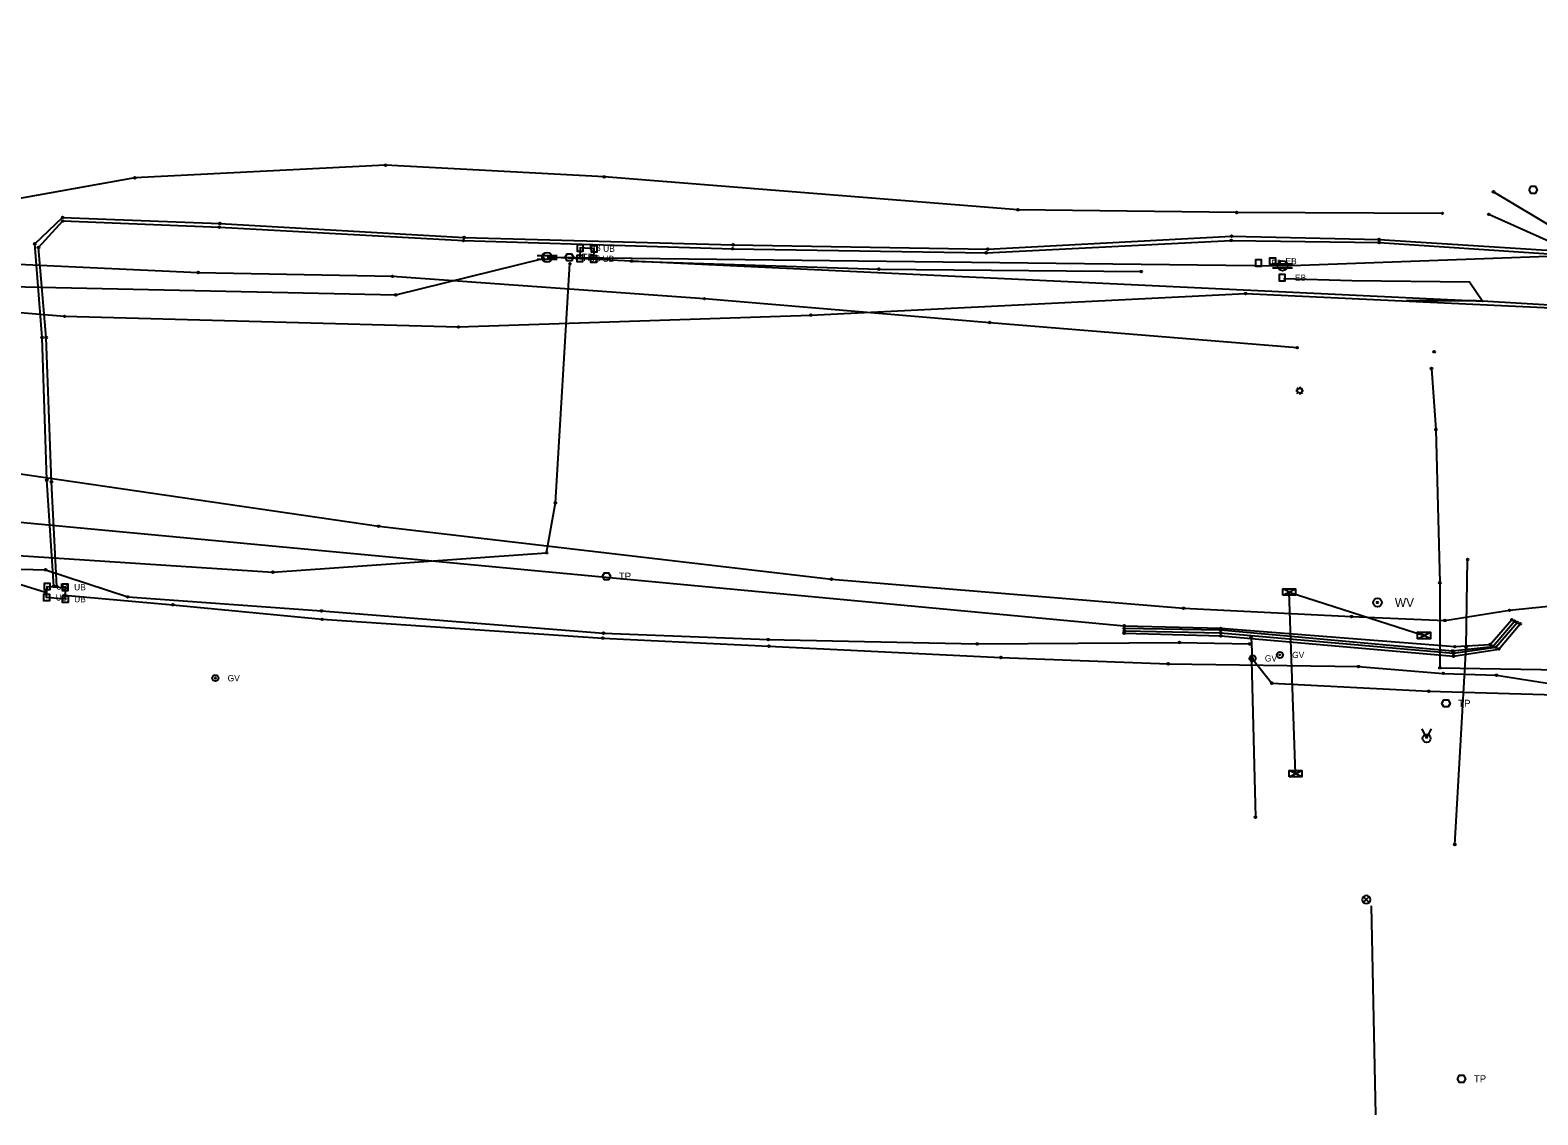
# Model space of a CAD drawing. Extents: x 20500343 to 20505311, y 7953484 to 7954193.
# Drawn here: x 20500991.2 to 20501326.9, y 7953798 to 7954039.6 of the extents above; entities that cross this region are included whole.
import ezdxf

# ---------------------------------------------------------------- set-up
doc = ezdxf.new("R2010")
doc.units = 0
for name, color, linetype in [('C-PROP-LINE-LOT', 7, 'Continuous'), ('V-ANNO-BNDY', 7, 'Continuous'), ('V-ANNO-NOTE', 7, 'Continuous'), ('V-CTRL-HVPT', 7, 'Continuous'), ('V-MON-FND', 7, 'Continuous'), ('V-SITE-FENC', 7, 'Continuous'), ('V-SSWR-STRC', 7, 'Continuous'), ('VF-NODE-MISC', 7, 'Continuous')]:
    doc.layers.add(name, color=color, linetype=linetype)

msp = doc.modelspace()

# ---------------------------------------------------------------- linework, layer by layer
at = {"layer": 'C-PROP-LINE-LOT'}
msp.add_line((20501289.71, 7953844.5), (20501290.73, 7953797.96), dxfattribs=at)
for points in [[(20500406.47, 7954039.57), (20500466.05, 7954034.11), (20500535.84, 7954027.4), (20500662.16, 7954017.11), (20500704.07, 7954013.07), (20500745.63, 7954009.37), (20500792.32, 7954005.22), (20500811.87, 7954003.45), (20500860.59, 7953999.05), (20500920.01, 7953993.63), (20500957.01, 7953989.31), (20500990.1, 7953987.34), (20501028.58, 7953985.6), (20501071.83, 7953984.74), (20501141.27, 7953979.76), (20501204.8, 7953974.46), (20501273.24, 7953968.85)], [(20500542.46, 7954022.99), (20500657.16, 7954010.94), (20500703.46, 7954006.71), (20500768.23, 7954003.33), (20500815.45, 7953998.2), (20500888.96, 7953989.5), (20500955.53, 7953983.16), (20501072.58, 7953980.59), (20501105.36, 7953988.74)], [(20500542.46, 7954013.94), (20500614.61, 7954008.93), (20500657.56, 7954005.52), (20500702.03, 7954001.63), (20500823.93, 7953990.08), (20500894.24, 7953984.51), (20500998.83, 7953975.83), (20501086.53, 7953973.45), (20501164.96, 7953976.11), (20501261.79, 7953980.89), (20501339.33, 7953977.27), (20501419.74, 7953970.03), (20501525.89, 7953965.34), (20501551.15, 7953963.49), (20501624.16, 7953957.55)], [(20501305.59, 7953998.76), (20501259.79, 7953998.96), (20501211.09, 7953999.57), (20501118.97, 7954006.88), (20501070.28, 7954009.47), (20501014.48, 7954006.68), (20500962.69, 7953997.37), (20500913.01, 7953999.39), (20500862.37, 7954004.75), (20500819.48, 7954008.4), (20500817.42, 7954012.31)], [(20501316.97, 7954003.56), (20501331.13, 7953995.08), (20501366.04, 7953982.93), (20501414.04, 7953978.62), (20501439.53, 7953975.27), (20501515.39, 7953971.55), (20501543.03, 7953969.36), (20501590.25, 7953966.08), (20501636.14, 7953963.16), (20501689.01, 7953958.28), (20501726.44, 7953956.52), (20501746.18, 7953958.43), (20501775.61, 7953959.04)], [(20500996.43, 7953915.71), (20500994.86, 7953939.31), (20500993.84, 7953971.13), (20500992.21, 7953991.99), (20500998.39, 7953997.86), (20501033.4, 7953996.49), (20501087.77, 7953993.38), (20501147.66, 7953991.76), (20501204.37, 7953990.78), (20501258.68, 7953993.69), (20501291.5, 7953992.96), (20501367.31, 7953988.1), (20501415.06, 7953984.51), (20501437.58, 7953981.75), (20501512.96, 7953981.34), (20501564.43, 7953975.75), (20501615.72, 7953972.77), (20501679.29, 7953965.51), (20501737.55, 7953960.19), (20501775.55, 7953956.71)], [(20501315.95, 7953998.55), (20501330.06, 7953992.29), (20501366.28, 7953980.24), (20501414.18, 7953976.37), (20501439.46, 7953973.28), (20501446.74, 7953968.11), (20501452.28, 7953949.16), (20501456.12, 7953922.73), (20501455.01, 7953897.31), (20501452.69, 7953873.02), (20501450.67, 7953841.46)], [(20500997.07, 7953915.68), (20500995.89, 7953938.94), (20500994.71, 7953971.1), (20500993, 7953991.18), (20500998.42, 7953997.06), (20501033.28, 7953995.67), (20501087.63, 7953992.68), (20501147.58, 7953990.88), (20501204.03, 7953989.96), (20501258.58, 7953992.74), (20501291.52, 7953992.27), (20501367.1, 7953987.19), (20501414.72, 7953983.8), (20501438.34, 7953980.22), (20501512.8, 7953980.63), (20501564.51, 7953974.63), (20501615.49, 7953972.13), (20501679.12, 7953964.62), (20501737.42, 7953959.32), (20501775.43, 7953955.89)], [(20501106.27, 7953988.97), (20501270.01, 7953987.09), (20501461.7, 7953994.07)], [(20501106.16, 7953923.17), (20501108.1, 7953934.3), (20501111.35, 7953987.56)], [(20501270.23, 7953984.25), (20501285.41, 7953983.78), (20501311.63, 7953983.5), (20501314.64, 7953979.15), (20501106.27, 7953988.97)], [(20501125.08, 7953988.13), (20501180.15, 7953986.34), (20501238.55, 7953985.78)], [(20501297.64, 7953979.33), (20501313.17, 7953979.32), (20501384.83, 7953975.15), (20501444.4, 7953969.74), (20501500.9, 7953964.74), (20501525.63, 7953962.76), (20501557.44, 7953960.37)], [(20500520.98, 7953977.28), (20500560.2, 7953972.18), (20500580.11, 7953968.09), (20500618.43, 7953964.47), (20500633.81, 7953963.45), (20500668.21, 7953960.34), (20500693.49, 7953957.8), (20500747.72, 7953955.96), (20500802.14, 7953953.65), (20500876.21, 7953950.48), (20500928.48, 7953945.92), (20500984.31, 7953941.41), (20501068.76, 7953929.07), (20501169.59, 7953917.28), (20501247.95, 7953910.8), (20501285.38, 7953908.94), (20501306.14, 7953908.1), (20501320.57, 7953910.34), (20501331.41, 7953911.48)], [(20500469.9, 7953970.65), (20500505.35, 7953968.7), (20500522.37, 7953967.11), (20500565.63, 7953966.99), (20500619.43, 7953961.41), (20500633.65, 7953961.99), (20500668.11, 7953958.55), (20500688.24, 7953956.38), (20500722.3, 7953952.32), (20500751.12, 7953948.12), (20500793.42, 7953946.39), (20500829.09, 7953943.31), (20500867.84, 7953939.12), (20500927.83, 7953934.54), (20500971.05, 7953923.41), (20500978.23, 7953919.45), (20500994.58, 7953914.36)], [(20500542.27, 7953966.39), (20500567.09, 7953964.35), (20500611.73, 7953958.49), (20500625.61, 7953958.17), (20500630.34, 7953957.23), (20500641.04, 7953945.21), (20500677.24, 7953941.24), (20500710.61, 7953939.53), (20500749.41, 7953937.97), (20500784.55, 7953934.93), (20500831.09, 7953929.74), (20500863.89, 7953925.18), (20500925.53, 7953920.74), (20500962.01, 7953920.15), (20500972.45, 7953919.98), (20500994.6, 7953919.38), (20501012.87, 7953913.32), (20501056.03, 7953910.21), (20501118.83, 7953905.25), (20501155.51, 7953903.82), (20501202, 7953902.86), (20501247.06, 7953903.19), (20501262.67, 7953902.86)], [(20501303.19, 7953964.19), (20501304.16, 7953950.59), (20501305.04, 7953916.44), (20501305.05, 7953897.56), (20501336.58, 7953897.02), (20501416.18, 7953891.49), (20501472.56, 7953887.01)], [(20500798.27, 7953938.75), (20500868.59, 7953931.82), (20500926.05, 7953926.61), (20501045.21, 7953918.84), (20501106.16, 7953923.17)], [(20500968.33, 7953931.91), (20501234.75, 7953906.92), (20501256.26, 7953906.33), (20501308.38, 7953902.25), (20501316.23, 7953902.74), (20501321.08, 7953908.26)], [(20501308.36, 7953858.15), (20501310.89, 7953902.15), (20501311.23, 7953921.69)], [(20500998.83, 7953913.68), (20501022.94, 7953911.59), (20501056.17, 7953908.34), (20501118.67, 7953904.16), (20501155.66, 7953902.37), (20501207.31, 7953899.83), (20501244.54, 7953898.43), (20501286.93, 7953897.81), (20501305.79, 7953896.3), (20501317.66, 7953895.88), (20501451.4, 7953874.84), (20501522.75, 7953865.03), (20501559.04, 7953858.38), (20501592.55, 7953848.31), (20501608.82, 7953843.84), (20501626.02, 7953848.37), (20501659.58, 7953855.08), (20501681.27, 7953854.69), (20501701.7, 7953853.44), (20501722.46, 7953851.13), (20501765.84, 7953847.22)], [(20501272.89, 7953873.96), (20501271.49, 7953914.42), (20501301.52, 7953904.73)], [(20501234.76, 7953905.25), (20501256.28, 7953904.66), (20501308.05, 7953900.12), (20501318.18, 7953901.72), (20501322.91, 7953907.33)], [(20501234.77, 7953906.33), (20501256.28, 7953905.98), (20501307.87, 7953901.29), (20501316.83, 7953902.31), (20501321.64, 7953907.92)], [(20501234.79, 7953905.75), (20501256.21, 7953905.36), (20501308.08, 7953900.78), (20501317.52, 7953902.1), (20501322.24, 7953907.64)], [(20501263.02, 7953904.3), (20501263.23, 7953899.59), (20501267.6, 7953894.11), (20501302.56, 7953892.31), (20501415.59, 7953889.07), (20501446.52, 7953886.98), (20501469.46, 7953879.66), (20501523.96, 7953857.45), (20501561.35, 7953852.73), (20501613.91, 7953852.27), (20501680.57, 7953850.9), (20501710.93, 7953846.81), (20501733.66, 7953845.08), (20501733.32, 7953834.72), (20501764.02, 7953830.92)], [(20501263.07, 7953899.12), (20501263.97, 7953864.25)]]:
    msp.add_lwpolyline(points, dxfattribs=at)
at = {"layer": 'V-ANNO-BNDY'}
for p, q in [((20501269.63, 7953984.27), (20501269.63, 7953984.27)), ((20501268.96, 7953969.75), (20501268.96, 7953969.75)), ((20501303.76, 7953967.94), (20501303.76, 7953967.94)), ((20501273.1, 7953959.9), (20501273.1, 7953959.9))]:
    msp.add_line(p, q, dxfattribs=at)
for centre, radius in [((20501263.33, 7953899.64), 0.685), ((20501269.41, 7953900.4), 0.685), ((20501269.41, 7953900.4), 0.114), ((20501263.33, 7953899.64), 0.114), ((20501032.39, 7953895.23), 0.685), ((20501032.39, 7953895.23), 0.114)]:
    msp.add_circle(centre, radius, dxfattribs=at)
at = {"layer": 'V-ANNO-NOTE'}
for centre in [(20501070.28, 7954009.47), (20501014.48, 7954006.68), (20501118.97, 7954006.88), (20501316.97, 7954003.56), (20500998.39, 7953997.86), (20501211.09, 7953999.57), (20501259.79, 7953998.96), (20501305.59, 7953998.76), (20501315.95, 7953998.55), (20500998.42, 7953997.06), (20501033.28, 7953995.67), (20501033.4, 7953996.49), (20500992.21, 7953991.99), (20500993, 7953991.18), (20501087.63, 7953992.68), (20501087.77, 7953993.38), (20501147.58, 7953990.88), (20501147.66, 7953991.76), (20501204.37, 7953990.78), (20501258.58, 7953992.74), (20501258.68, 7953993.69), (20501291.5, 7953992.96), (20501291.52, 7953992.27), (20501105.36, 7953988.74), (20501111.35, 7953987.56), (20501125.08, 7953988.13), (20501204.03, 7953989.96), (20501028.58, 7953985.6), (20501071.83, 7953984.74), (20501180.15, 7953986.34), (20501238.55, 7953985.78), (20501261.79, 7953980.89), (20501072.58, 7953980.59), (20501141.27, 7953979.76), (20500998.83, 7953975.83), (20501164.96, 7953976.11), (20501204.8, 7953974.46), (20500993.84, 7953971.13), (20500994.71, 7953971.1), (20501086.53, 7953973.45), (20501273.24, 7953968.85), (20501303.76, 7953967.94), (20501303.19, 7953964.19), (20501304.16, 7953950.59), (20500994.86, 7953939.31), (20500995.89, 7953938.94), (20501108.1, 7953934.3), (20501068.76, 7953929.07), (20501106.16, 7953923.17), (20501106.16, 7953923.17), (20501311.23, 7953921.69), (20500994.6, 7953919.38), (20501045.21, 7953918.84), (20501169.59, 7953917.28), (20500994.58, 7953914.36), (20500996.43, 7953915.71), (20500997.07, 7953915.68), (20500998.83, 7953913.68), (20501305.04, 7953916.44), (20501012.87, 7953913.32), (20501022.94, 7953911.59), (20501056.03, 7953910.21), (20501247.95, 7953910.8), (20501320.57, 7953910.34), (20501056.17, 7953908.34), (20501234.75, 7953906.92), (20501285.38, 7953908.94), (20501306.14, 7953908.1), (20501321.08, 7953908.26), (20501321.64, 7953907.92), (20501322.24, 7953907.64), (20501322.91, 7953907.33), (20501118.67, 7953904.16), (20501118.83, 7953905.25), (20501155.51, 7953903.82), (20501234.76, 7953905.25), (20501234.77, 7953906.33), (20501234.79, 7953905.75), (20501256.21, 7953905.36), (20501256.26, 7953906.33), (20501256.28, 7953905.98), (20501256.28, 7953904.66), (20501263.02, 7953904.3), (20501155.66, 7953902.37), (20501202, 7953902.86), (20501247.06, 7953903.19), (20501262.67, 7953902.86), (20501307.87, 7953901.29), (20501308.05, 7953900.12), (20501308.08, 7953900.78), (20501308.38, 7953902.25), (20501310.89, 7953902.15), (20501316.23, 7953902.74), (20501316.83, 7953902.31), (20501317.52, 7953902.1), (20501318.18, 7953901.72), (20501207.31, 7953899.83), (20501244.54, 7953898.43), (20501263.07, 7953899.12), (20501263.23, 7953899.59), (20501286.93, 7953897.81), (20501305.05, 7953897.56), (20501267.6, 7953894.11), (20501305.79, 7953896.3), (20501317.66, 7953895.88), (20501302.56, 7953892.31), (20501263.97, 7953864.25), (20501308.36, 7953858.15)]:
    msp.add_circle(centre, 0.2, dxfattribs=at)
at = {"layer": 'V-CTRL-HVPT'}
for p, q in [((20501104.07, 7953989.41), (20501108.47, 7953989.41)), ((20501104.07, 7953988.53), (20501108.47, 7953988.53)), ((20501267.81, 7953987.53), (20501272.21, 7953987.53)), ((20501267.81, 7953986.65), (20501272.21, 7953986.65)), ((20501272.97, 7953959.28), (20501273.3, 7953959.28)), ((20501273.23, 7953959.9), (20501273.46, 7953959.67)), ((20501273.23, 7953958.67), (20501273.46, 7953958.9)), ((20501273.84, 7953960.15), (20501273.84, 7953959.82)), ((20501273.84, 7953958.74), (20501273.84, 7953958.41)), ((20501274.22, 7953959.67), (20501274.45, 7953959.9)), ((20501274.22, 7953958.9), (20501274.45, 7953958.67)), ((20501274.38, 7953959.28), (20501274.71, 7953959.28))]:
    msp.add_line(p, q, dxfattribs=at)
for centre, radius in [((20501106.27, 7953988.97), 1.1), ((20501270.01, 7953987.09), 1.1), ((20501273.84, 7953959.28), 0.543)]:
    msp.add_circle(centre, radius, dxfattribs=at)
at = {"layer": 'V-MON-FND'}
for points in [[(20501324.91, 7954003.99), (20501325.36, 7954004.78), (20501326.28, 7954004.78), (20501326.73, 7954003.99), (20501326.28, 7954003.2), (20501325.36, 7954003.2), (20501324.91, 7954003.99)], [(20501110.3, 7953988.97), (20501110.75, 7953989.76), (20501111.67, 7953989.76), (20501112.12, 7953988.97), (20501111.67, 7953988.18), (20501110.75, 7953988.18), (20501110.3, 7953988.97)], [(20501305.49, 7953889.62), (20501305.94, 7953890.41), (20501306.86, 7953890.41), (20501307.31, 7953889.62), (20501306.86, 7953888.83), (20501305.94, 7953888.83), (20501305.49, 7953889.62)]]:
    msp.add_lwpolyline(points, dxfattribs=at)
for points in [[(20501113.54, 7953988.7), (20501116.64, 7953988.6), (20501116.74, 7953990.87), (20501113.63, 7953991.05)], [(20501113.54, 7953988.7), (20501116.64, 7953988.6), (20501116.74, 7953990.87), (20501113.63, 7953991.05)], [(20500998.97, 7953912.83), (20500994.83, 7953913.2), (20500994.93, 7953915.63), (20500998.96, 7953915.46)], [(20500998.97, 7953912.83), (20500994.83, 7953913.2), (20500994.93, 7953915.63), (20500998.96, 7953915.46)]]:
    msp.add_lwpolyline(points, close=True, dxfattribs=at)
at = {"layer": 'V-SITE-FENC'}
for points in [[(20501113.63, 7953990.37), (20501113.63, 7953990.37), (20501114.32, 7953990.37), (20501114.32, 7953991.74), (20501112.94, 7953991.74), (20501112.94, 7953990.37), (20501113.63, 7953990.37)], [(20501116.74, 7953990.18), (20501116.74, 7953990.18), (20501117.43, 7953990.18), (20501117.43, 7953991.55), (20501116.05, 7953991.55), (20501116.05, 7953990.18), (20501116.74, 7953990.18)], [(20501113.54, 7953988.01), (20501113.54, 7953988.01), (20501114.23, 7953988.01), (20501114.23, 7953989.38), (20501112.85, 7953989.38), (20501112.85, 7953988.01), (20501113.54, 7953988.01)], [(20501116.64, 7953987.91), (20501116.64, 7953987.91), (20501117.33, 7953987.91), (20501117.33, 7953989.28), (20501115.95, 7953989.28), (20501115.95, 7953987.91), (20501116.64, 7953987.91)], [(20501264.65, 7953987.03), (20501264.65, 7953987.03), (20501265.34, 7953987.03), (20501265.34, 7953988.4), (20501263.96, 7953988.4), (20501263.96, 7953987.03), (20501264.65, 7953987.03)], [(20501267.82, 7953987.42), (20501267.82, 7953987.42), (20501268.51, 7953987.42), (20501268.51, 7953988.79), (20501267.13, 7953988.79), (20501267.13, 7953987.42), (20501267.82, 7953987.42)], [(20501269.93, 7953983.75), (20501269.93, 7953983.75), (20501270.62, 7953983.75), (20501270.62, 7953985.12), (20501269.24, 7953985.12), (20501269.24, 7953983.75), (20501269.93, 7953983.75)], [(20501118.58, 7953917.93), (20501119.03, 7953918.72), (20501119.95, 7953918.72), (20501120.4, 7953917.93), (20501119.95, 7953917.14), (20501119.03, 7953917.14), (20501118.58, 7953917.93)], [(20500994.83, 7953912.51), (20500994.83, 7953912.51), (20500995.52, 7953912.51), (20500995.52, 7953913.88), (20500994.14, 7953913.88), (20500994.14, 7953912.51), (20500994.83, 7953912.51)], [(20500994.93, 7953914.95), (20500994.93, 7953914.95), (20500995.62, 7953914.95), (20500995.62, 7953916.32), (20500994.24, 7953916.32), (20500994.24, 7953914.95), (20500994.93, 7953914.95)], [(20500998.96, 7953914.77), (20500998.96, 7953914.77), (20500999.65, 7953914.77), (20500999.65, 7953916.14), (20500998.27, 7953916.14), (20500998.27, 7953914.77), (20500998.96, 7953914.77)], [(20500998.97, 7953912.14), (20500998.97, 7953912.14), (20500999.66, 7953912.14), (20500999.66, 7953913.51), (20500998.28, 7953913.51), (20500998.28, 7953912.14), (20500998.97, 7953912.14)], [(20501308.96, 7953805.98), (20501309.41, 7953806.78), (20501310.33, 7953806.78), (20501310.78, 7953805.98), (20501310.33, 7953805.19), (20501309.41, 7953805.19), (20501308.96, 7953805.98)]]:
    msp.add_lwpolyline(points, dxfattribs=at)
at = {"layer": 'V-SSWR-STRC'}
for points in [[(20501270.05, 7953913.7), (20501270.05, 7953915.14), (20501272.93, 7953915.14), (20501272.93, 7953913.7)], [(20501300.08, 7953904.01), (20501300.08, 7953905.45), (20501302.96, 7953905.45), (20501302.96, 7953904.01)], [(20501271.45, 7953873.24), (20501271.45, 7953874.68), (20501274.33, 7953874.68), (20501274.33, 7953873.24)]]:
    msp.add_lwpolyline(points, close=True, dxfattribs=at)
for points in [[(20501270.05, 7953913.7), (20501272.93, 7953915.14), (20501272.93, 7953913.7), (20501270.05, 7953915.14)], [(20501300.08, 7953904.01), (20501302.96, 7953905.45), (20501302.96, 7953904.01), (20501300.08, 7953905.45)], [(20501271.45, 7953873.24), (20501274.33, 7953874.68), (20501274.33, 7953873.24), (20501271.45, 7953874.68)], [(20501288.02, 7953845.28), (20501288.66, 7953845.91), (20501288.02, 7953846.55)], [(20501289.3, 7953846.55), (20501288.66, 7953845.91), (20501289.3, 7953845.28)]]:
    msp.add_lwpolyline(points, dxfattribs=at)
for radius in [0.971, 0.162]:
    msp.add_circle((20501291.14, 7953912.08), radius, dxfattribs=at)
for start, end in [(135, 225), (45, 135), (315, 45), (225, 315)]:
    msp.add_arc((20501288.66, 7953845.91), 0.899, start, end, dxfattribs=at)
at = {"layer": 'VF-NODE-MISC'}
for p, q in [((20501300.99, 7953883.98), (20501302.07, 7953881.82)), ((20501302.07, 7953881.82), (20501303.15, 7953883.98))]:
    msp.add_line(p, q, dxfattribs=at)
msp.add_circle((20501302.07, 7953881.82), 0.897, dxfattribs=at)

# ---------------------------------------------------------------- texts
at = {"layer": 'V-ANNO-BNDY'}
for p in [(20501266.07, 7953898.94), (20501272.15, 7953899.7), (20501035.13, 7953894.53)]:
    msp.add_text('GV', height=1.399, dxfattribs=at).set_placement(p)
at = {"layer": 'V-MON-FND'}
for p in [(20501113.95, 7953988.17), (20501309.14, 7953888.82)]:
    msp.add_text('TP', height=1.599, dxfattribs=at).set_placement(p)
at = {"layer": 'V-SITE-FENC'}
for s, height, p in [('UB', 1.399, (20501115.62, 7953990.37)), ('UB', 1.399, (20501118.73, 7953990.19)), ('UB', 1.399, (20501115.53, 7953988.02)), ('UB', 1.399, (20501118.63, 7953987.92)), ('EB', 1.399, (20501267.49, 7953987.01)), ('EB', 1.399, (20501270.66, 7953987.41)), ('EB', 1.399, (20501272.77, 7953983.74)), ('TP', 1.599, (20501122.23, 7953917.13)), ('UB', 1.399, (20500996.82, 7953912.51)), ('UB', 1.399, (20500996.92, 7953914.95)), ('UB', 1.399, (20501000.95, 7953914.78)), ('UB', 1.399, (20501000.96, 7953912.14)), ('TP', 1.599, (20501312.61, 7953805.19))]:
    msp.add_text(s, height=height, dxfattribs=at).set_placement(p)
at = {"layer": 'V-SSWR-STRC'}
msp.add_text('WV', height=1.982, dxfattribs=at).set_placement((20501295.02, 7953911.09))

doc.saveas('drawing.dxf')
